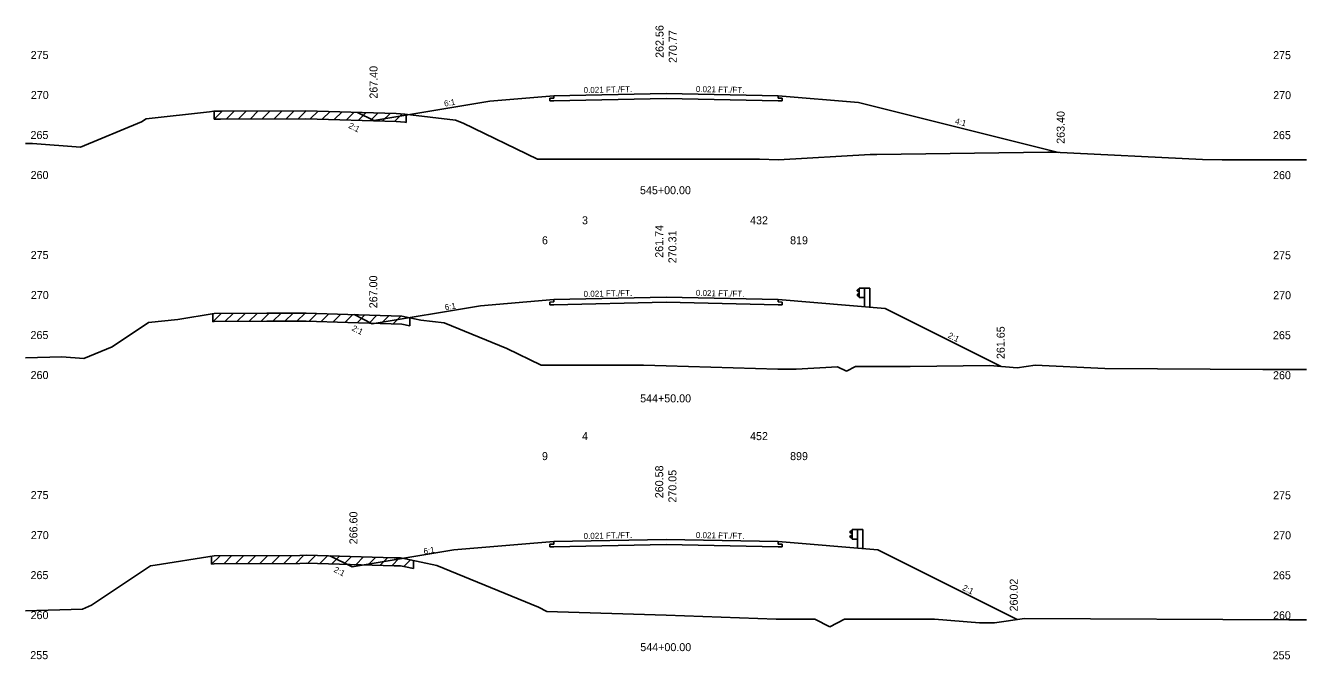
# Model space of a CAD drawing. Extents: x 2967 to 4323, y -3677 to -817.
# Drawn here: x 3555.3 to 3715.3, y -2054.8 to -1975.6 of the extents above; entities that cross this region are included whole.
import ezdxf

# ---------------------------------------------------------------- set-up
doc = ezdxf.new("R2010")
doc.units = 0
for name, color, linetype in [('Level 1', 7, 'Continuous'), ('Level 10', 7, 'Continuous'), ('Level 11', 7, 'Continuous'), ('Level 12', 7, 'Continuous'), ('Level 24', 7, 'Continuous'), ('Level 3', 7, 'Continuous'), ('Level 32', 7, 'Continuous'), ('Level 33', 7, 'Continuous'), ('Level 59', 7, 'Continuous'), ('Level 6', 7, 'Continuous'), ('Level 60', 7, 'Continuous'), ('Level 61', 7, 'Continuous'), ('Level 7', 7, 'Continuous')]:
    doc.layers.add(name, color=color, linetype=linetype)

msp = doc.modelspace()

# ---------------------------------------------------------------- linework, layer by layer
at = {"layer": 'Level 11'}
for p, q in [((3621.35, -1984.66), (3620.85, -1984.67)), ((3620.85, -1984.67), (3620.85, -1985.01)), ((3620.85, -1985.01), (3621.35, -1985)), ((3621.35, -1984.36), (3621.35, -1984.66)), ((3649.35, -1984.66), (3649.35, -1984.36)), ((3649.85, -1984.67), (3649.35, -1984.66)), ((3649.35, -1985), (3649.85, -1985.01)), ((3649.85, -1985.01), (3649.85, -1984.67)), ((3621.35, -2010.13), (3620.85, -2010.14)), ((3620.85, -2010.14), (3620.85, -2010.48)), ((3620.85, -2010.48), (3621.35, -2010.47)), ((3621.35, -2009.83), (3621.35, -2010.13)), ((3649.35, -2010.13), (3649.35, -2009.83)), ((3649.85, -2010.14), (3649.35, -2010.13)), ((3649.35, -2010.47), (3649.85, -2010.48)), ((3649.85, -2010.48), (3649.85, -2010.14)), ((3621.35, -2040.38), (3620.85, -2040.39)), ((3620.85, -2040.39), (3620.85, -2040.73)), ((3620.85, -2040.73), (3621.35, -2040.72)), ((3621.35, -2040.08), (3621.35, -2040.38)), ((3649.35, -2040.38), (3649.35, -2040.08)), ((3649.85, -2040.39), (3649.35, -2040.38)), ((3649.35, -2040.72), (3649.85, -2040.73)), ((3649.85, -2040.73), (3649.85, -2040.39))]:
    msp.add_line(p, q, dxfattribs=at)
at = {"layer": 'Level 12'}
for p, q in [((3635.35, -1984.71), (3621.35, -1985)), ((3649.35, -1985), (3635.35, -1984.71)), ((3635.35, -2010.17), (3621.35, -2010.47)), ((3649.35, -2010.47), (3635.35, -2010.17)), ((3635.35, -2040.43), (3621.35, -2040.72)), ((3649.35, -2040.72), (3635.35, -2040.43))]:
    msp.add_line(p, q, dxfattribs=at)
at = {"layer": 'Level 24'}
for p, q in [((3659.48, -2008.47), (3659.21, -2008.67)), ((3659.21, -2008.67), (3659.21, -2008.72)), ((3659.21, -2008.72), (3659.48, -2008.92)), ((3659.21, -2009.24), (3659.48, -2009.04)), ((3659.21, -2009.29), (3659.21, -2009.24)), ((3659.48, -2009.49), (3659.21, -2009.29)), ((3659.48, -2009.56), (3659.48, -2008.4)), ((3659.48, -2008.4), (3660.15, -2008.4)), ((3659.48, -2009.56), (3660.15, -2009.56)), ((3660.15, -2008.4), (3660.15, -2010.73)), ((3660.15, -2008.4), (3660.81, -2008.4)), ((3660.81, -2008.4), (3660.81, -2010.78)), ((3658.6, -2038.65), (3658.32, -2038.85)), ((3658.32, -2038.85), (3658.32, -2038.9)), ((3658.32, -2038.9), (3658.6, -2039.1)), ((3658.32, -2039.42), (3658.6, -2039.22)), ((3658.32, -2039.47), (3658.32, -2039.42)), ((3658.6, -2039.67), (3658.32, -2039.47)), ((3658.6, -2039.75), (3658.6, -2038.58)), ((3658.6, -2038.58), (3659.26, -2038.58)), ((3658.6, -2039.75), (3659.26, -2039.75)), ((3659.26, -2038.58), (3659.26, -2040.91)), ((3659.26, -2038.58), (3659.93, -2038.58)), ((3659.93, -2038.58), (3659.93, -2040.96))]:
    msp.add_line(p, q, dxfattribs=at)
at = {"layer": 'Level 59'}
for p, q in [((3621.35, -1984.36), (3635.35, -1984.07)), ((3635.35, -1984.07), (3649.35, -1984.36)), ((3621.35, -2009.83), (3635.35, -2009.53)), ((3635.35, -2009.53), (3649.35, -2009.83)), ((3621.35, -2040.08), (3635.35, -2039.79)), ((3635.35, -2039.79), (3649.35, -2040.08))]:
    msp.add_line(p, q, dxfattribs=at)
at = {"layer": 'Level 6'}
for p, q in [((3613.35, -1985.02), (3621.35, -1984.36)), ((3649.35, -1984.36), (3659.38, -1985.19)), ((3612.19, -2010.59), (3621.35, -2009.83)), ((3649.35, -2009.83), (3662.71, -2010.94)), ((3608.86, -2041.12), (3621.35, -2040.08)), ((3649.35, -2040.08), (3661.82, -2041.12))]:
    msp.add_line(p, q, dxfattribs=at)
at = {"layer": 'Level 60'}
for p, q in [((3570.41, -1987.23), (3578.3, -1986.38)), ((3578.3, -1986.38), (3578.87, -1986.29)), ((3578.87, -1986.29), (3579.69, -1986.29)), ((3579.69, -1986.29), (3590.35, -1986.23)), ((3590.35, -1986.23), (3601.63, -1986.58)), ((3601.63, -1986.58), (3602.74, -1986.67)), ((3602.74, -1986.67), (3609.04, -1987.41)), ((3562.2, -1990.8), (3569.84, -1987.61)), ((3569.84, -1987.61), (3570.41, -1987.23)), ((3609.04, -1987.41), (3610, -1987.8)), ((3610, -1987.8), (3619.3, -1992.27)), ((3555.35, -1990.34), (3556.22, -1990.32)), ((3556.22, -1990.32), (3562.2, -1990.8)), ((3649.42, -1992.35), (3660.85, -1991.7)), ((3660.85, -1991.7), (3661.7, -1991.7)), ((3661.7, -1991.7), (3683.06, -1991.42)), ((3683.06, -1991.42), (3683.77, -1991.41)), ((3683.77, -1991.41), (3702.35, -1992.34)), ((3619.3, -1992.27), (3635.35, -1992.28)), ((3635.35, -1992.28), (3647.04, -1992.29)), ((3647.04, -1992.29), (3649.42, -1992.35)), ((3702.35, -1992.34), (3704.82, -1992.35)), ((3704.82, -1992.35), (3715.35, -1992.35)), ((3566.17, -2015.72), (3570.71, -2012.7)), ((3570.71, -2012.7), (3574.35, -2012.31)), ((3574.35, -2012.31), (3578.89, -2011.57)), ((3578.89, -2011.57), (3585.48, -2011.54)), ((3585.48, -2011.54), (3590.39, -2011.52)), ((3590.39, -2011.52), (3595.59, -2011.68)), ((3595.59, -2011.68), (3602.33, -2011.89)), ((3602.33, -2011.89), (3604.72, -2012.41)), ((3604.72, -2012.41), (3607.63, -2012.75)), ((3607.63, -2012.75), (3615.47, -2015.95)), ((3562.64, -2017.19), (3566.17, -2015.72)), ((3615.47, -2015.95), (3619.75, -2018.01)), ((3555.35, -2017.11), (3559.88, -2016.97)), ((3559.88, -2016.97), (3562.64, -2017.19)), ((3619.75, -2018.01), (3632.52, -2018.02)), ((3632.52, -2018.02), (3635.35, -2018.1)), ((3635.35, -2018.1), (3649.31, -2018.52)), ((3649.31, -2018.52), (3651.59, -2018.52)), ((3651.59, -2018.52), (3656.76, -2018.22)), ((3656.76, -2018.22), (3657.9, -2018.78)), ((3657.9, -2018.78), (3659.04, -2018.21)), ((3659.04, -2018.21), (3665.84, -2018.21)), ((3665.84, -2018.21), (3675.81, -2018.08)), ((3675.81, -2018.08), (3679.21, -2018.36)), ((3679.21, -2018.36), (3681.48, -2018.02)), ((3681.48, -2018.02), (3690.17, -2018.45)), ((3690.17, -2018.45), (3709.9, -2018.56)), ((3709.9, -2018.56), (3715.35, -2018.56)), ((3563.58, -2048), (3570.96, -2043.09)), ((3570.96, -2043.09), (3571.53, -2043.03)), ((3571.53, -2043.03), (3578.9, -2041.83)), ((3578.9, -2041.83), (3589.59, -2041.79)), ((3589.59, -2041.79), (3590.42, -2041.77)), ((3590.42, -2041.77), (3601.4, -2042.11)), ((3601.4, -2042.11), (3602.19, -2042.12)), ((3602.19, -2042.12), (3602.81, -2042.21)), ((3602.81, -2042.21), (3606.72, -2043.05)), ((3606.72, -2043.05), (3619.44, -2048.25)), ((3562.44, -2048.5), (3563.58, -2048)), ((3555.35, -2048.71), (3562.44, -2048.5)), ((3619.44, -2048.25), (3620.46, -2048.82)), ((3620.46, -2048.82), (3621.79, -2048.86)), ((3621.79, -2048.86), (3635.35, -2049.27)), ((3635.35, -2049.27), (3649.13, -2049.77)), ((3649.13, -2049.77), (3652.87, -2049.76)), ((3652.87, -2049.76), (3653.94, -2049.78)), ((3653.94, -2049.78), (3655.8, -2050.71)), ((3655.8, -2050.71), (3657.66, -2049.78)), ((3657.66, -2049.78), (3668.89, -2049.77)), ((3668.89, -2049.77), (3674.53, -2050.23)), ((3674.53, -2050.23), (3676.4, -2050.24)), ((3676.4, -2050.24), (3680.14, -2049.68)), ((3680.14, -2049.68), (3713.15, -2049.84)), ((3713.15, -2049.84), (3715.33, -2049.86)), ((3715.33, -2049.86), (3715.35, -2049.86))]:
    msp.add_line(p, q, dxfattribs=at)
at = {"layer": 'Level 61'}
for p, q in [((3579.91, -1986.29), (3578.91, -1987.29)), ((3578.91, -1986.29), (3578.91, -1987.29)), ((3581.41, -1986.28), (3580.41, -1987.28)), ((3582.91, -1986.27), (3581.91, -1987.28)), ((3584.41, -1986.26), (3583.41, -1987.27)), ((3585.91, -1986.26), (3584.91, -1987.26)), ((3587.41, -1986.25), (3586.41, -1987.25)), ((3588.91, -1986.24), (3587.91, -1987.25)), ((3590.41, -1986.23), (3589.41, -1987.24)), ((3591.88, -1986.28), (3590.91, -1987.25)), ((3593.38, -1986.33), (3592.41, -1987.3)), ((3594.88, -1986.37), (3593.91, -1987.34)), ((3596.38, -1986.42), (3595.41, -1987.39)), ((3597.88, -1986.47), (3596.91, -1987.44)), ((3599.38, -1986.51), (3598.41, -1987.48)), ((3600.88, -1986.56), (3599.91, -1987.53)), ((3602.35, -1986.64), (3601.41, -1987.58)), ((3602.88, -1987.69), (3602.88, -1986.69)), ((3578.91, -1987.29), (3579.69, -1987.29)), ((3579.69, -1987.29), (3590.35, -1987.23)), ((3590.35, -1987.23), (3601.63, -1987.58)), ((3601.63, -1987.58), (3602.74, -1987.67)), ((3602.74, -1987.67), (3602.88, -1987.69)), ((3579.78, -2011.57), (3578.75, -2012.59)), ((3578.75, -2011.59), (3578.75, -2012.59)), ((3578.75, -2012.59), (3578.89, -2012.57)), ((3578.89, -2012.57), (3585.48, -2012.54)), ((3581.26, -2011.56), (3580.25, -2012.57)), ((3582.76, -2011.56), (3581.75, -2012.56)), ((3584.26, -2011.55), (3583.25, -2012.55)), ((3585.76, -2011.54), (3584.75, -2012.55)), ((3585.48, -2012.54), (3590.39, -2012.52)), ((3587.26, -2011.53), (3586.25, -2012.54)), ((3588.76, -2011.53), (3587.75, -2012.53)), ((3590.26, -2011.52), (3589.25, -2012.52)), ((3590.39, -2012.52), (3595.59, -2012.68)), ((3591.72, -2011.56), (3590.75, -2012.53)), ((3593.22, -2011.61), (3592.25, -2012.58)), ((3594.72, -2011.65), (3593.75, -2012.62)), ((3596.22, -2011.7), (3595.25, -2012.67)), ((3595.59, -2012.68), (3602.33, -2012.89)), ((3597.72, -2011.75), (3596.75, -2012.72)), ((3599.22, -2011.79), (3598.25, -2012.76)), ((3600.72, -2011.84), (3599.75, -2012.81)), ((3602.22, -2011.89), (3601.25, -2012.86)), ((3603.35, -2013.11), (3603.35, -2012.11)), ((3602.33, -2012.89), (3603.35, -2013.11)), ((3578.59, -2042.88), (3578.9, -2042.83)), ((3579.65, -2041.83), (3578.59, -2042.88)), ((3578.59, -2041.88), (3578.59, -2042.88)), ((3578.9, -2042.83), (3589.59, -2042.79)), ((3581.1, -2041.82), (3580.1, -2042.83)), ((3582.6, -2041.82), (3581.6, -2042.82)), ((3584.1, -2041.81), (3583.1, -2042.81)), ((3585.6, -2041.8), (3584.6, -2042.81)), ((3587.1, -2041.8), (3586.1, -2042.8)), ((3588.6, -2041.79), (3587.6, -2042.79)), ((3590.11, -2041.77), (3589.1, -2042.79)), ((3589.59, -2042.79), (3590.42, -2042.77)), ((3590.42, -2042.77), (3601.4, -2043.11)), ((3591.56, -2041.8), (3590.6, -2042.77)), ((3593.06, -2041.85), (3592.1, -2042.82)), ((3594.56, -2041.9), (3593.6, -2042.87)), ((3596.06, -2041.94), (3595.1, -2042.91)), ((3597.56, -2041.99), (3596.6, -2042.96)), ((3599.06, -2042.04), (3598.1, -2043.01)), ((3600.56, -2042.08), (3599.6, -2043.05)), ((3602.07, -2042.12), (3601.1, -2043.1)), ((3601.4, -2043.11), (3602.19, -2043.12)), ((3602.19, -2043.12), (3602.81, -2043.21)), ((3603.43, -2042.34), (3602.6, -2043.18)), ((3603.81, -2043.42), (3603.81, -2042.42)), ((3602.81, -2043.21), (3603.81, -2043.42))]:
    msp.add_line(p, q, dxfattribs=at)
at = {"layer": 'Level 7'}
for p, q in [((3598.84, -1987.44), (3613.35, -1985.02)), ((3659.38, -1985.19), (3684.37, -1991.44)), ((3598.84, -1987.44), (3596.82, -1986.43)), ((3598.66, -2012.84), (3612.19, -2010.59)), ((3662.71, -2010.94), (3677.23, -2018.2)), ((3598.66, -2012.84), (3596.38, -2011.7)), ((3596.13, -2043.24), (3608.86, -2041.12)), ((3661.82, -2041.12), (3679.22, -2049.82)), ((3596.13, -2043.24), (3593.36, -2041.86))]:
    msp.add_line(p, q, dxfattribs=at)

# ---------------------------------------------------------------- texts
at = {"layer": 'Level 1'}
for s, p in [('3', (3624.85, -2000.42)), ('432', (3645.85, -2000.42)), ('6', (3619.85, -2002.92)), ('819', (3650.85, -2002.92)), ('4', (3624.85, -2027.39)), ('452', (3645.85, -2027.39)), ('9', (3619.85, -2029.89)), ('899', (3650.85, -2029.89))]:
    msp.add_text(s, height=1, dxfattribs=at).set_placement(p)
at = {"layer": 'Level 10'}
for s, p in [('262.56', (3635.04, -1979.62)), ('261.74', (3635, -2004.6)), ('260.58', (3635, -2034.65))]:
    msp.add_text(s, height=1, rotation=90, dxfattribs=at).set_placement(p)
for s, p in [('545+00.00', (3632.1, -1996.66)), ('544+50.00', (3632.12, -2022.67)), ('544+00.00', (3632.14, -2053.76))]:
    msp.add_text(s, height=1, dxfattribs=at).set_placement(p)
at = {"layer": 'Level 3'}
for s, p in [(' 275', (3555.61, -1979.76)), (' 275', (3710.82, -1979.78)), (' 270', (3555.63, -1984.76)), (' 270', (3710.83, -1984.78)), (' 265', (3555.59, -1989.76)), (' 265', (3710.8, -1989.78)), (' 260', (3555.6, -1994.76)), (' 260', (3710.81, -1994.78)), (' 275', (3555.61, -2004.76)), (' 275', (3710.82, -2004.78)), (' 270', (3555.63, -2009.76)), (' 270', (3710.83, -2009.78)), (' 265', (3555.59, -2014.76)), (' 265', (3710.8, -2014.78)), (' 260', (3555.6, -2019.76)), (' 260', (3710.81, -2019.78)), (' 275', (3555.61, -2034.76)), (' 275', (3710.82, -2034.78)), (' 270', (3555.63, -2039.76)), (' 270', (3710.83, -2039.78)), (' 265', (3555.59, -2044.76)), (' 265', (3710.8, -2044.78)), (' 260', (3555.6, -2049.76)), (' 260', (3710.81, -2049.78)), (' 255', (3555.56, -2054.76)), (' 255', (3710.76, -2054.78))]:
    msp.add_text(s, height=1, dxfattribs=at).set_placement(p)
at = {"layer": 'Level 32'}
for s, rotation, p in [('0.021 FT./FT.', 1.1916, (3625.06, -1984.03)), ('0.021 FT./FT.', 358.8084, (3639.07, -1983.89)), ('6:1', 9.4623, (3607.69, -1985.71)), ('2:1', 333.435, (3595.61, -1988.33)), ('4:1', 345.9638, (3671.4, -1987.85)), ('0.021 FT./FT.', 1.1916, (3625.06, -2009.5)), ('0.021 FT./FT.', 358.8084, (3639.07, -2009.36)), ('6:1', 9.4623, (3607.78, -2011.17)), ('2:1', 333.435, (3596.02, -2013.65)), ('2:1', 333.435, (3670.5, -2014.55)), ('0.021 FT./FT.', 1.1916, (3625.06, -2039.75)), ('0.021 FT./FT.', 358.8084, (3639.07, -2039.62)), ('6:1', 9.4623, (3605.12, -2041.66)), ('2:1', 333.435, (3593.77, -2043.82)), ('2:1', 333.435, (3672.3, -2046.08))]:
    msp.add_text(s, height=0.75, rotation=rotation, dxfattribs=at).set_placement(p)
at = {"layer": 'Level 33'}
for s, p in [('267.40', (3599.31, -1984.72)), ('263.40', (3685.15, -1990.36)), ('267.00', (3599.28, -2010.91)), ('261.65', (3677.66, -2017.26)), ('266.60', (3596.8, -2040.41)), ('260.02', (3679.29, -2048.8))]:
    msp.add_text(s, height=1, rotation=90, dxfattribs=at).set_placement(p)
at = {"layer": 'Level 59'}
for s, p in [(' 270.77', (3636.7, -1980.63)), (' 270.31', (3636.65, -2005.66)), (' 270.05', (3636.65, -2035.57))]:
    msp.add_text(s, height=1, rotation=90, dxfattribs=at).set_placement(p)

doc.saveas('drawing.dxf')
